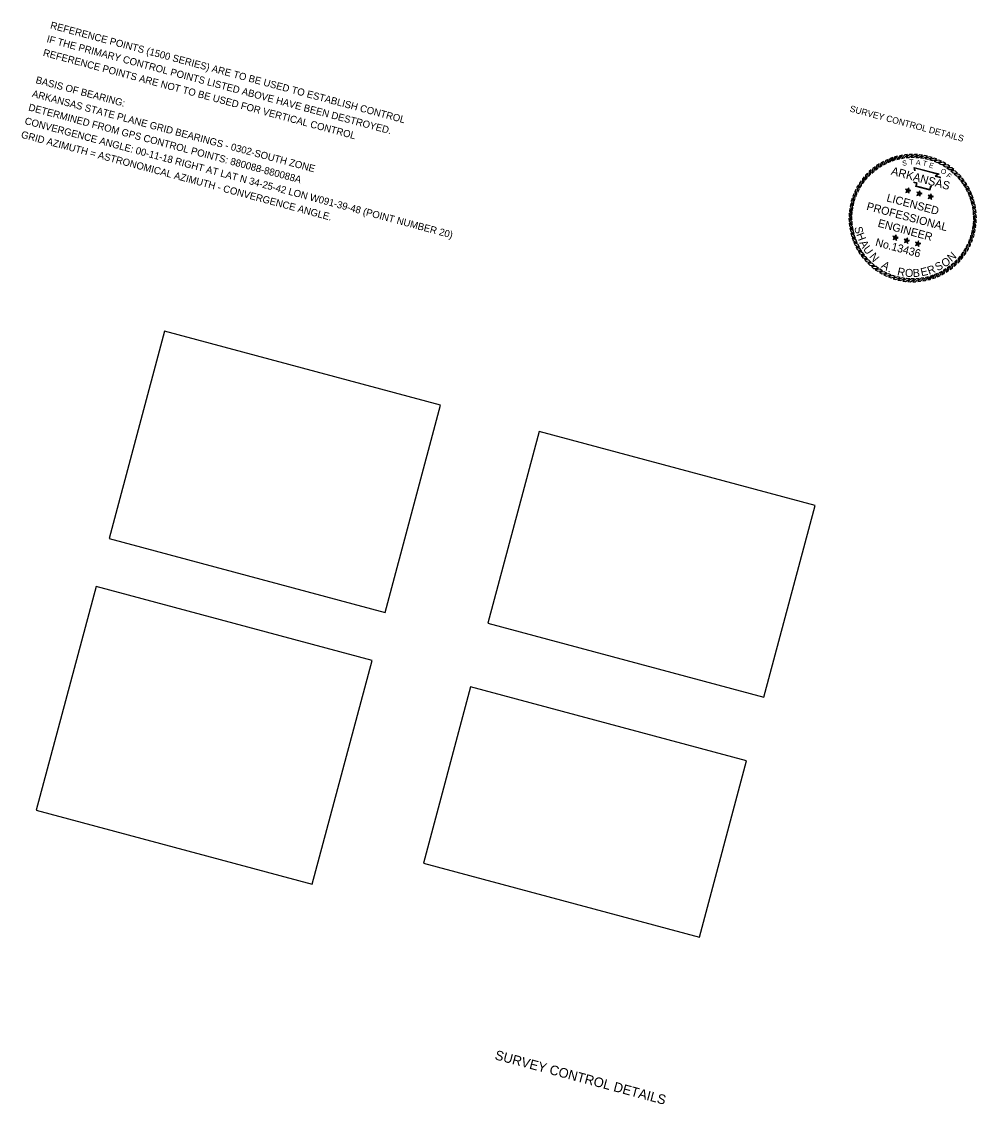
# Model space of a CAD drawing. Extents: x 1222460 to 1224160, y 2071531 to 2072851.
# Drawn here: x 1223266 to 1224160, y 2071531 to 2072546 of the extents above; entities that cross this region are included whole.
import ezdxf

# ---------------------------------------------------------------- set-up
doc = ezdxf.new("R2010")
doc.units = 0
for name, color, linetype in [('1', 7, 'Continuous'), ('60', 7, 'Continuous'), ('Default', 7, 'Continuous'), ('G-ANNO-SYMB', 7, 'Continuous')]:
    doc.layers.add(name, color=color, linetype=linetype)

msp = doc.modelspace()

# ---------------------------------------------------------------- linework, layer by layer
at = {"layer": 'Default'}
for points in [[(1223347.6, 2072061.5), (1223606.2, 2071992.2), (1223658.2, 2072186.4), (1223399.6, 2072255.7)], [(1223702.3, 2071982.1), (1223960.9, 2071912.8), (1224009, 2072092.4), (1223750.4, 2072161.7)], [(1223279.4, 2071807.1), (1223538, 2071737.8), (1223594.1, 2071947.1), (1223335.5, 2072016.4)], [(1223642.1, 2071757.4), (1223900.7, 2071688.1), (1223944.9, 2071853.1), (1223686.3, 2071922.4)]]:
    msp.add_lwpolyline(points, close=True, dxfattribs=at)
at = {"layer": 'G-ANNO-SYMB'}
for points in [[(1224081.9, 2072418.3), (1224079.5, 2072417.4), (1224077.1, 2072413.5), (1224079.7, 2072414.6)], [(1224086.4, 2072419.5), (1224083.9, 2072418.9), (1224081.3, 2072415.2), (1224083.9, 2072416)], [(1224091, 2072420.5), (1224088.5, 2072420), (1224085.6, 2072416.5), (1224088.2, 2072417.2)], [(1224095.7, 2072421), (1224093.1, 2072420.8), (1224089.9, 2072417.5), (1224092.6, 2072417.9)], [(1224100.4, 2072421.2), (1224097.8, 2072421.2), (1224094.3, 2072418.2), (1224097.1, 2072418.4)], [(1224105, 2072421), (1224102.5, 2072421.2), (1224098.8, 2072418.5), (1224101.6, 2072418.5)], [(1224109.7, 2072420.5), (1224107.1, 2072420.8), (1224103.3, 2072418.4), (1224106, 2072418.2)], [(1224114.3, 2072419.6), (1224111.8, 2072420.1), (1224107.7, 2072418), (1224110.5, 2072417.6)], [(1224118.8, 2072418.3), (1224116.3, 2072419.1), (1224112.1, 2072417.3), (1224114.8, 2072416.7)], [(1224065.3, 2072409.7), (1224063.3, 2072408.2), (1224062.2, 2072403.7), (1224064.3, 2072405.5)], [(1224069.2, 2072412.4), (1224067, 2072411), (1224065.7, 2072406.6), (1224067.9, 2072408.2)], [(1224073.3, 2072414.6), (1224071, 2072413.4), (1224069.3, 2072409.2), (1224071.7, 2072410.7)], [(1224077.5, 2072416.6), (1224075.2, 2072415.6), (1224073.1, 2072411.5), (1224075.6, 2072412.8)], [(1224123.2, 2072416.7), (1224120.8, 2072417.7), (1224116.5, 2072416.2), (1224119.1, 2072415.4)], [(1224127.5, 2072414.8), (1224125.1, 2072415.9), (1224120.7, 2072414.8), (1224123.3, 2072413.7)], [(1224131.5, 2072412.5), (1224129.3, 2072413.8), (1224124.8, 2072413), (1224127.3, 2072411.8)], [(1224135.4, 2072409.9), (1224133.3, 2072411.4), (1224128.8, 2072411), (1224131.2, 2072409.5)], [(1224139.1, 2072407), (1224137.1, 2072408.6), (1224132.6, 2072408.6), (1224134.8, 2072407)], [(1224055, 2072400.2), (1224053.4, 2072398.2), (1224053.5, 2072393.6), (1224055.1, 2072395.9)], [(1224058.2, 2072403.6), (1224056.4, 2072401.8), (1224056.1, 2072397.2), (1224057.9, 2072399.3)], [(1224061.6, 2072406.8), (1224059.7, 2072405.1), (1224059.1, 2072400.6), (1224061, 2072402.6)], [(1224142.6, 2072403.8), (1224140.7, 2072405.6), (1224136.2, 2072405.9), (1224138.3, 2072404.1)], [(1224145.8, 2072400.4), (1224144.1, 2072402.3), (1224139.5, 2072403), (1224141.5, 2072401)], [(1224148.7, 2072396.7), (1224147.1, 2072398.8), (1224142.7, 2072399.8), (1224144.5, 2072397.7)], [(1224047.3, 2072388.5), (1224046.2, 2072386.2), (1224047.3, 2072381.8), (1224048.3, 2072384.3)], [(1224049.6, 2072392.6), (1224048.3, 2072390.4), (1224049, 2072385.9), (1224050.3, 2072388.4)], [(1224052.1, 2072396.5), (1224050.7, 2072394.4), (1224051.1, 2072389.8), (1224052.5, 2072392.2)], [(1224096.1, 2072387.3), (1224095.7, 2072388.3), (1224093.8, 2072388.8), (1224095.1, 2072387.3)], [(1224096.1, 2072387.3), (1224096.9, 2072388), (1224096.8, 2072390), (1224095.7, 2072388.3)], [(1224096.1, 2072387.3), (1224097, 2072386.8), (1224098.8, 2072387.5), (1224096.9, 2072388)], [(1224151.3, 2072392.9), (1224149.9, 2072395), (1224145.5, 2072396.4), (1224147.2, 2072394.1)], [(1224153.6, 2072388.8), (1224152.4, 2072391), (1224148.1, 2072392.7), (1224149.6, 2072390.4)], [(1224155.6, 2072384.5), (1224154.5, 2072386.9), (1224150.4, 2072388.9), (1224151.7, 2072386.4)], [(1224043.7, 2072379.9), (1224043, 2072377.4), (1224044.8, 2072373.2), (1224045.4, 2072375.9)], [(1224045.3, 2072384.3), (1224044.4, 2072381.9), (1224045.8, 2072377.5), (1224046.7, 2072380.2)], [(1224096.1, 2072387.3), (1224095.1, 2072387.3), (1224094, 2072385.6), (1224095.8, 2072386.3)], [(1224096.1, 2072387.3), (1224095.8, 2072386.3), (1224097.1, 2072384.8), (1224097, 2072386.8)], [(1224106.6, 2072384.5), (1224106.3, 2072385.5), (1224104.4, 2072386), (1224105.6, 2072384.5)], [(1224106.6, 2072384.5), (1224105.6, 2072384.5), (1224104.5, 2072382.8), (1224106.4, 2072383.5)], [(1224106.6, 2072384.5), (1224107.5, 2072385.2), (1224107.3, 2072387.1), (1224106.3, 2072385.5)], [(1224106.6, 2072384.5), (1224106.4, 2072383.5), (1224107.6, 2072382), (1224107.5, 2072383.9)], [(1224106.6, 2072384.5), (1224107.5, 2072383.9), (1224109.4, 2072384.6), (1224107.5, 2072385.2)], [(1224117.2, 2072381.7), (1224116.8, 2072382.7), (1224114.9, 2072383.2), (1224116.1, 2072381.6)], [(1224117.2, 2072381.7), (1224116.1, 2072381.6), (1224115.1, 2072380), (1224116.9, 2072380.7)], [(1224117.2, 2072381.7), (1224118, 2072382.3), (1224117.9, 2072384.3), (1224116.8, 2072382.7)], [(1224117.2, 2072381.7), (1224116.9, 2072380.7), (1224118.2, 2072379.1), (1224118.1, 2072381.1)], [(1224117.2, 2072381.7), (1224118.1, 2072381.1), (1224119.9, 2072381.8), (1224118, 2072382.3)], [(1224157.2, 2072380.1), (1224156.3, 2072382.6), (1224152.4, 2072384.9), (1224153.5, 2072382.4)], [(1224158.5, 2072375.6), (1224157.8, 2072378.1), (1224154.1, 2072380.8), (1224155, 2072378.1)], [(1224041.5, 2072370.7), (1224041.2, 2072368.2), (1224043.6, 2072364.3), (1224043.8, 2072367.1)], [(1224042.5, 2072375.3), (1224041.9, 2072372.8), (1224044, 2072368.8), (1224044.4, 2072371.5)], [(1224159.4, 2072371), (1224158.9, 2072373.6), (1224155.4, 2072376.5), (1224156.1, 2072373.8)], [(1224160, 2072366.4), (1224159.7, 2072368.9), (1224156.4, 2072372.1), (1224156.9, 2072369.4)], [(1224160.2, 2072361.7), (1224160.1, 2072364.3), (1224157.1, 2072367.7), (1224157.3, 2072365)], [(1224040.8, 2072361.4), (1224040.9, 2072358.8), (1224043.9, 2072355.4), (1224043.7, 2072358.2)], [(1224041, 2072366.1), (1224040.9, 2072363.5), (1224043.6, 2072359.9), (1224043.6, 2072362.6)], [(1224159.4, 2072352.4), (1224159.8, 2072354.9), (1224157.4, 2072358.8), (1224157.2, 2072356)], [(1224160, 2072357), (1224160.1, 2072359.6), (1224157.4, 2072363.3), (1224157.4, 2072360.5)], [(1224041, 2072356.7), (1224041.3, 2072354.2), (1224044.6, 2072351), (1224044.1, 2072353.7)], [(1224041.6, 2072352.1), (1224042.1, 2072349.6), (1224045.6, 2072346.6), (1224044.9, 2072349.3)], [(1224042.5, 2072347.5), (1224043.2, 2072345), (1224046.9, 2072342.4), (1224046, 2072345)], [(1224157.3, 2072343.3), (1224158, 2072345.7), (1224156.2, 2072349.9), (1224155.6, 2072347.2)], [(1224158.5, 2072347.8), (1224159.1, 2072350.3), (1224157, 2072354.3), (1224156.5, 2072351.6)], [(1224043.8, 2072343), (1224044.7, 2072340.6), (1224048.6, 2072338.2), (1224047.5, 2072340.8)], [(1224045.4, 2072338.6), (1224046.5, 2072336.2), (1224050.6, 2072334.2), (1224049.3, 2072336.7)], [(1224084.3, 2072343.2), (1224083.9, 2072344.2), (1224082, 2072344.7), (1224083.2, 2072343.1)], [(1224084.3, 2072343.2), (1224083.2, 2072343.1), (1224082.2, 2072341.5), (1224084, 2072342.2)], [(1224084.3, 2072343.2), (1224085.1, 2072343.9), (1224085, 2072345.8), (1224083.9, 2072344.2)], [(1224084.3, 2072343.2), (1224084, 2072342.2), (1224085.3, 2072340.7), (1224085.2, 2072342.6)], [(1224084.3, 2072343.2), (1224085.2, 2072342.6), (1224087, 2072343.3), (1224085.1, 2072343.9)], [(1224094.8, 2072340.4), (1224094.4, 2072341.4), (1224092.5, 2072341.9), (1224093.8, 2072340.3)], [(1224094.8, 2072340.4), (1224093.8, 2072340.3), (1224092.7, 2072338.7), (1224094.6, 2072339.4)], [(1224094.8, 2072340.4), (1224095.6, 2072341), (1224095.5, 2072343), (1224094.4, 2072341.4)], [(1224094.8, 2072340.4), (1224094.6, 2072339.4), (1224095.8, 2072337.8), (1224095.7, 2072339.8)], [(1224094.8, 2072340.4), (1224095.7, 2072339.8), (1224097.5, 2072340.5), (1224095.6, 2072341)], [(1224105.4, 2072337.6), (1224105, 2072338.5), (1224103.1, 2072339), (1224104.3, 2072337.5)], [(1224105.4, 2072337.6), (1224104.3, 2072337.5), (1224103.2, 2072335.8), (1224105.1, 2072336.5)], [(1224105.4, 2072337.6), (1224106.2, 2072338.2), (1224106.1, 2072340.2), (1224105, 2072338.5)], [(1224105.4, 2072337.6), (1224105.1, 2072336.5), (1224106.3, 2072335), (1224106.2, 2072337)], [(1224105.4, 2072337.6), (1224106.2, 2072337), (1224108.1, 2072337.7), (1224106.2, 2072338.2)], [(1224151.4, 2072330.5), (1224152.7, 2072332.7), (1224152, 2072337.2), (1224150.7, 2072334.8)], [(1224153.7, 2072334.6), (1224154.8, 2072336.9), (1224153.7, 2072341.4), (1224152.7, 2072338.8)], [(1224155.7, 2072338.9), (1224156.6, 2072341.3), (1224155.1, 2072345.6), (1224154.3, 2072342.9)], [(1224047.4, 2072334.3), (1224048.6, 2072332.1), (1224052.9, 2072330.4), (1224051.4, 2072332.7)], [(1224049.7, 2072330.3), (1224051.1, 2072328.1), (1224055.5, 2072326.7), (1224053.8, 2072329)], [(1224146, 2072322.9), (1224147.6, 2072324.9), (1224147.5, 2072329.5), (1224145.9, 2072327.2)], [(1224148.8, 2072326.6), (1224150.3, 2072328.7), (1224149.9, 2072333.3), (1224148.5, 2072330.9)], [(1224052.3, 2072326.4), (1224053.9, 2072324.3), (1224058.3, 2072323.3), (1224056.5, 2072325.4)], [(1224055.2, 2072322.7), (1224056.9, 2072320.8), (1224061.5, 2072320.1), (1224059.5, 2072322.1)], [(1224058.4, 2072319.3), (1224060.3, 2072317.5), (1224064.8, 2072317.2), (1224062.7, 2072319)], [(1224135.7, 2072313.4), (1224137.7, 2072314.9), (1224138.7, 2072319.4), (1224136.6, 2072317.6)], [(1224139.3, 2072316.3), (1224141.3, 2072318), (1224141.9, 2072322.5), (1224140, 2072320.5)], [(1224142.8, 2072319.5), (1224144.6, 2072321.3), (1224144.9, 2072325.9), (1224143.1, 2072323.8)], [(1224061.9, 2072316.1), (1224063.8, 2072314.5), (1224068.4, 2072314.5), (1224066.2, 2072316.1)], [(1224065.5, 2072313.2), (1224067.7, 2072311.8), (1224072.2, 2072312.1), (1224069.8, 2072313.6)], [(1224069.4, 2072310.6), (1224071.7, 2072309.3), (1224076.2, 2072310.1), (1224073.7, 2072311.3)], [(1224073.5, 2072308.3), (1224075.9, 2072307.2), (1224080.3, 2072308.3), (1224077.7, 2072309.4)], [(1224077.8, 2072306.4), (1224080.2, 2072305.5), (1224084.5, 2072306.9), (1224081.9, 2072307.8)], [(1224110, 2072302.7), (1224112.5, 2072303.1), (1224115.4, 2072306.6), (1224112.7, 2072306)], [(1224114.6, 2072303.6), (1224117, 2072304.2), (1224119.7, 2072308), (1224117.1, 2072307.1)], [(1224119.1, 2072304.9), (1224121.5, 2072305.7), (1224123.8, 2072309.6), (1224121.3, 2072308.6)], [(1224123.5, 2072306.5), (1224125.8, 2072307.5), (1224127.8, 2072311.6), (1224125.4, 2072310.4)], [(1224127.7, 2072308.5), (1224130, 2072309.7), (1224131.7, 2072313.9), (1224129.3, 2072312.5)], [(1224131.8, 2072310.8), (1224133.9, 2072312.2), (1224135.3, 2072316.5), (1224133.1, 2072314.9)], [(1224082.2, 2072304.8), (1224084.7, 2072304), (1224088.9, 2072305.8), (1224086.2, 2072306.5)], [(1224086.7, 2072303.5), (1224089.2, 2072303), (1224093.3, 2072305.1), (1224090.5, 2072305.5)], [(1224091.3, 2072302.6), (1224093.8, 2072302.3), (1224097.7, 2072304.7), (1224095, 2072304.9)], [(1224096, 2072302.1), (1224098.5, 2072301.9), (1224102.2, 2072304.7), (1224099.4, 2072304.6)], [(1224100.6, 2072301.9), (1224103.2, 2072302), (1224106.7, 2072305), (1224103.9, 2072304.7)], [(1224105.3, 2072302.1), (1224107.9, 2072302.4), (1224111.1, 2072305.6), (1224108.3, 2072305.2)]]:
    msp.add_lwpolyline(points, close=True, dxfattribs=at)
for points in [[(1224102.5, 2072405.9), (1224101.9, 2072409.1), (1224125.2, 2072402.9), (1224122.6, 2072401), (1224124.1, 2072400.6), (1224125.5, 2072400.3), (1224126.7, 2072399.8)], [(1224102.8, 2072405.9), (1224102.4, 2072408.6), (1224124.3, 2072402.7), (1224121.7, 2072400.8), (1224124, 2072400.2), (1224125.3, 2072399.9), (1224126.6, 2072399.4)], [(1224118.1, 2072391.2), (1224117.6, 2072391), (1224117.4, 2072390.6), (1224116.9, 2072389.4), (1224116.5, 2072387.8), (1224103.5, 2072391.3), (1224104.1, 2072393.4), (1224104.2, 2072393.9), (1224103.7, 2072394.2), (1224101.9, 2072394.7), (1224101.7, 2072395.3)], [(1224117.9, 2072391.6), (1224117.3, 2072391.3), (1224117, 2072390.7), (1224116.5, 2072389.5), (1224116.2, 2072388.3), (1224104, 2072391.5), (1224104.4, 2072393.3), (1224104.6, 2072394.1), (1224103.9, 2072394.6), (1224102.2, 2072395), (1224102, 2072395.4)]]:
    msp.add_lwpolyline(points, dxfattribs=at)

# ---------------------------------------------------------------- texts
at = {"layer": '1'}
msp.add_text('SURVEY CONTROL DETAILS', height=6, rotation=345, dxfattribs=at).set_placement((1224041.1, 2072461.5))
at = {"layer": '60'}
msp.add_text('SURVEY CONTROL DETAILS', height=9, rotation=345, dxfattribs=at).set_placement((1223708.4, 2071573.7))
at = {"layer": 'Default'}
for s, p in [('REFERENCE POINTS (1500 SERIES) ARE TO BE USED TO ESTABLISH CONTROL ', (1223292, 2072539.3)), ('IF THE PRIMARY CONTROL POINTS LISTED ABOVE HAVE BEEN DESTROYED. ', (1223288.6, 2072526.5)), ('REFERENCE POINTS ARE NOT TO BE USED FOR VERTICAL CONTROL ', (1223285.2, 2072513.7)), ('BASIS OF BEARING: ', (1223278.3, 2072488.1)), ('ARKANSAS STATE PLANE GRID BEARINGS - 0302-SOUTH ZONE ', (1223274.9, 2072475.3)), ('DETERMINED FROM GPS CONTROL POINTS: 880088-880088A ', (1223271.5, 2072462.5)), ('CONVERGENCE ANGLE: 00-11-18 RIGHT AT LAT N 34-25-42 LON W091-39-48 (POINT NUMBER 20) ', (1223268, 2072449.8)), ('GRID AZIMUTH = ASTRONOMICAL AZIMUTH - CONVERGENCE ANGLE. ', (1223264.6, 2072437))]:
    msp.add_text(s, height=6.669, rotation=345, dxfattribs=at).set_placement(p)
at = {"layer": 'G-ANNO-SYMB'}
for s, height, rotation, p in [('ARKANSAS', 7.75, 345, (1224079.7, 2072402.4)), ('S', 4.75, 4.7726, (1224090.8, 2072410.6)), ('T', 4.75, 1.9015, (1224097.3, 2072411.7)), ('A', 4.75, 353.6788, (1224103.3, 2072411.6)), ('T', 4.75, 346.4789, (1224109.4, 2072411)), ('E', 4.75, 341.672, (1224115.3, 2072409.3)), ('O', 4.75, 326.2218, (1224126, 2072404.7)), ('F', 4.75, 320.3628, (1224131.5, 2072400.6)), ('LICENSED', 7.5, 345, (1224075.5, 2072377.4)), ('PROFESSIONAL', 7.5, 345, (1224056.7, 2072369.4)), ('ENGINEER', 7.5, 345, (1224067.3, 2072353.6)), ('S', 7.5, 283.1636, (1224045.7, 2072352.8)), ('H', 7.5, 290.619, (1224047.5, 2072346.3)), ('A', 7.5, 298.4472, (1224050.3, 2072338.4)), ('No.13436', 7.47, 345, (1224065, 2072335.7)), ('U', 7.5, 305.9026, (1224053.6, 2072332.5)), ('N', 7.5, 309.9326, (1224059.4, 2072325.2)), ('N', 7.5, 41.1007, (1224136.8, 2072320.3)), ('A', 7.5, 328.0991, (1224070.4, 2072315.6)), ('R', 7.5, 20.6597, (1224115.8, 2072308.5)), ('S', 7.5, 28.4878, (1224123.8, 2072311.7)), ('O', 7.5, 29.7757, (1224130, 2072315.1)), ('.', 7.5, 336.3, (1224076.9, 2072311.5)), ('R', 7.5, 348.2287, (1224085.6, 2072308.2)), ('O', 7.5, 356.4296, (1224093.1, 2072306.7)), ('B', 7.5, 3.885, (1224100.8, 2072306.3)), ('E', 7.5, 12.8315, (1224108.8, 2072307))]:
    msp.add_text(s, height=height, rotation=rotation, dxfattribs=at).set_placement(p)

doc.saveas('drawing.dxf')
